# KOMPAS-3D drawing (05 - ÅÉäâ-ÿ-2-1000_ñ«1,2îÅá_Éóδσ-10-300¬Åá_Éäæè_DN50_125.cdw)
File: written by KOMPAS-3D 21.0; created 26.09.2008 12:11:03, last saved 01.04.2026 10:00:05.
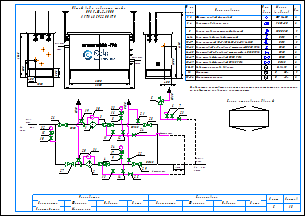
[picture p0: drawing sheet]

Sheets 1-2: A3, landscape

Document properties: Наименование: Макро:21; Автор: RaskoAdmin; Форматы листов документа: 2xA3; Полное имя файла: \\UR38nt01\Departments\КТО\КБ ПУРДГ\Заявки\Прайс-лист на типовые шкафы ГРПШ\ПРДГ_стандарт_20_03_2026\ПРДГ с РДСК\ПРДГ-Ш-2-1000_до1,2МПа_Рвых-10-300кПа_РДСК_DN50_125.cdw

Title block, sheet 1: Наименование: Пункт учета газа / ПУГ-Ш-400-Р / ЛГТИ.485922.001ТУ; designation: ЛГТИ.03.4411141; sheet number: 1; Количество листов документа: 2; organisation: ООО "ЭЛЬСТЕР Газэлектроника"; Форматы листов документа: A3; stored path: C:\Рабочие документы\Компас\ПУГ\Схема.cdw; Разработал: Устинов; Проверил: Кошкин; Утвердил: Кошкин
Title block, sheet 2: sheet number: 2; stored path: D:\Рабочие документы\Заявки\ПУРДГ\ПУРДГ-ШУЭО-2-100-Р 4411220.cdw; designation, second copy: ЛГТИ.03.4411141-

Views: Вид 1, Вид 2
Referenced files: wcvoit.frw
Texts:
  Normal
  Вход
  газа
  PDI
  Выход
  Р=     кПа
  DN125
  DN50
  DN20
  Импульс DN20
  ≥5DN
  HYSWLongFangSong
  № на
  схеме
  Усл.
  обозн.
  Марка
  (модель)
  Кол.
  Фильтр газовый фланцевый
  ФГ 16-50
  Регулятор давления газа
  РДCК-50
  Клапан предохранительный сбросной
  КПС DN20
  Кран шаровой газовый латунный
  DN15
  Кран кнопочный VE-РАСКО-НЗ-1,6-G1/2-М20
  Кран шаровой "под приварку" штуцерный DN20 PN16
  Кран шаровой "под приварку" штуцерный п/п DN20 PN16
  Кран шаровой фланцевый DN50 PN16
  Кран шаровой фланцевый DN125 PN16
  Индикатор перепада давления
  Delta 15
  Манометр
  Манометр-напоромер
  0...     МПа
  0...     кПа
  Общий вид и габариты шкафа
  ПРДГ-Ш-2-1000
  Выход газа
  Вход газа
  Схема открывания дверей
  Р=        МПа
  logo-rasko-ge.png
  Предприятие изготовитель может заменять комплектующие на аналогичные,
  не ухудшающие заявленных характеристик.
  Должность
  Конструктор
  Фамилия
  Подпись
  Дата
  Согласовано
  Максимкин
  Лист
  Листов
  POLYLINE_STYLE_0.18_RGB_0_0_0
  POLYLINE_STYLE_0.50_RGB_0_0_0
  POLYLINE_STYLE_0.34_RGB_0_0_0
  PHANTOM_RGB_0_0_0_SC_1_THICK_0.18
  K5LT_THIN_RGB_0_0_0_THICK_0.18
  K5LT32769_RGB_0_0_0_THICK_0.18
  K5LT12_RGB_0_0_0_SC_1_THICK_0.18
  K5LT_DASHED_RGB_0_0_0_SC_1_THICK_0.18
  ACISOTGL_RGB_0_0_0_SC_0.8_THICK_0.25
  CONTINUOUS_RGB_0_127_31_THICK_0.3
  CONTINUOUS_RGB_0_0_255_THICK_0.35
  CONTINUOUS_RGB_255_0_0_THICK_0.35
  POLYLINE_STYLE_0.25_RGB_0_0_0
  CONTINUOUS_RGB_0_0_0_THICK_0.5
  POLYLINE_STYLE_0.35_RGB_0_0_255
  CONTINUOUS_RGB_0_0_0_THICK_0.4
  CONTINUOUS_RGB_0_0_0_THICK_0.35
  Без оформления
Dimensions and other numbers on the sheet: 1; 2; 3; 4; 5; 10; 27; 28; 29; 23; 8; 12; 19; 20; 21; 22; 25; 24; 30; 31; 15; 16; 26; 6; 7; 11; 14; 13; 33; 1, 2; 3, 4; 6-14; 9; 15-17; 18-23; 24-25; 26-27; 28-29; 30-31; 32; 33-34; 400; 1050; 500; 305; 2500; 1565; 2800; 17; 34; 1000; 4130; 18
